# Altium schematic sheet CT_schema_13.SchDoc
size 389 x 385 mm
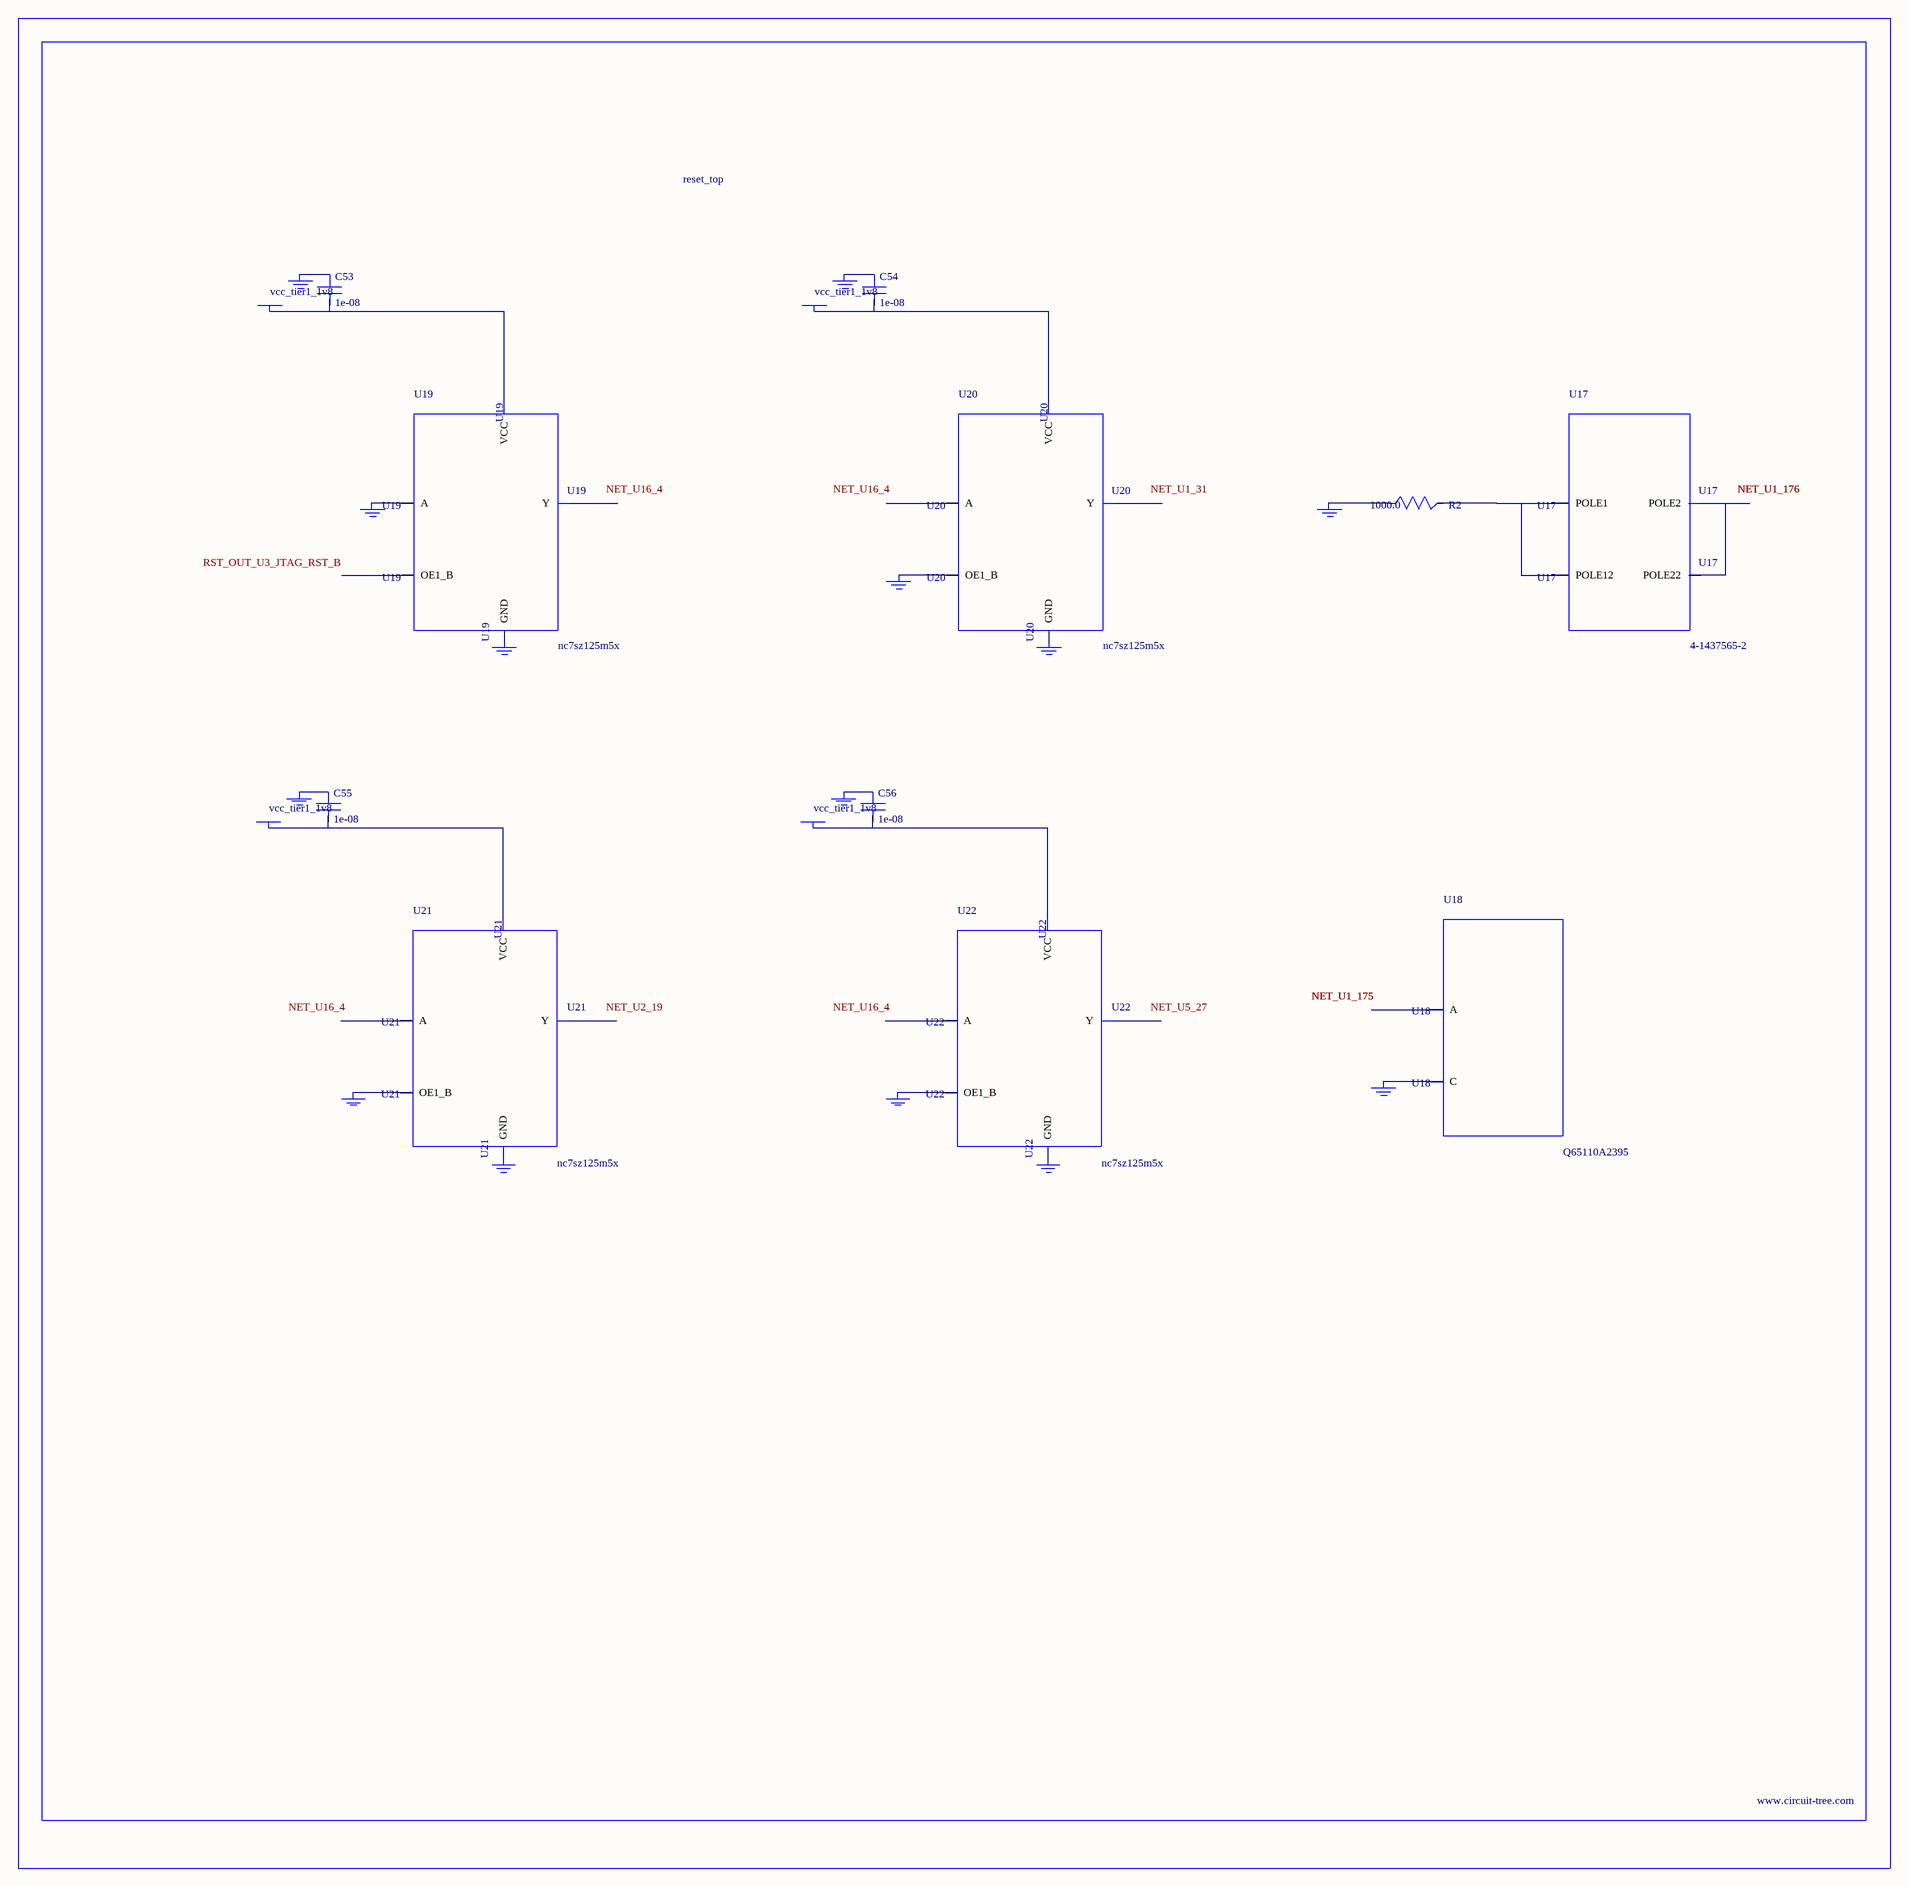
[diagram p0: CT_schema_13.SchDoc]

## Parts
BORDER12  (no value)
C53  1e-08  [C0402]
C54  1e-08  [C0402]
C55  1e-08  [C0402]
C56  1e-08  [C0402]
GND_INSTANCE_12_0  (no value)
GND_INSTANCE_12_1  (no value)
GND_INSTANCE_12_2  (no value)
GND_INSTANCE_12_3  (no value)
GND_INSTANCE_12_4  (no value)
GND_INSTANCE_12_5  (no value)
GND_INSTANCE_12_6  (no value)
GND_INSTANCE_12_7  (no value)
GND_INSTANCE_12_8  (no value)
GND_INSTANCE_12_9  (no value)
GND_INSTANCE_12_10  (no value)
GND_INSTANCE_12_11  (no value)
GND_INSTANCE_12_12  (no value)
GND_INSTANCE_12_13  (no value)
POWER_INSTANCE_12_0  vcc_tier1_1v8
POWER_INSTANCE_12_1  vcc_tier1_1v8
POWER_INSTANCE_12_2  vcc_tier1_1v8
POWER_INSTANCE_12_3  vcc_tier1_1v8
R2  1000.0  [R0603]
U17  4-1437565-2  [SW_4-1437565-2]
U18  Q65110A2395  [LGM67K-G1J2-24-Z]
U19  nc7sz125m5x  [NC7SZ125M5X]
U20  nc7sz125m5x  [NC7SZ125M5X]
U21  nc7sz125m5x  [NC7SZ125M5X]
U22  nc7sz125m5x  [NC7SZ125M5X]

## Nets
NetC53_1: C53.1 GND_INSTANCE_12_2.0(GND)
NetC53_2: C53.2 POWER_INSTANCE_12_0.0(PWR) U19.5(VCC)
NetC54_1: C54.1 GND_INSTANCE_12_5.0(GND)
NetC54_2: C54.2 POWER_INSTANCE_12_1.0(PWR) U20.5(VCC)
NetC55_1: C55.1 GND_INSTANCE_12_8.0(GND)
NetC55_2: C55.2 POWER_INSTANCE_12_2.0(PWR) U21.5(VCC)
NetC56_1: C56.1 GND_INSTANCE_12_11.0(GND)
NetC56_2: C56.2 POWER_INSTANCE_12_3.0(PWR) U22.5(VCC)
NetGND_INSTANCE_12_0_0: GND_INSTANCE_12_0.0(GND) R2.1
NetGND_INSTANCE_12_1_0: GND_INSTANCE_12_1.0(GND) U18.C
NetGND_INSTANCE_12_3_0: GND_INSTANCE_12_3.0(GND) U19.2(A)
NetGND_INSTANCE_12_4_0: GND_INSTANCE_12_4.0(GND) U19.3(GND)
NetGND_INSTANCE_12_6_0: GND_INSTANCE_12_6.0(GND) U20.1(OE1_B)
NetGND_INSTANCE_12_7_0: GND_INSTANCE_12_7.0(GND) U20.3(GND)
NetGND_INSTANCE_12_9_0: GND_INSTANCE_12_9.0(GND) U21.1(OE1_B)
NetGND_INSTANCE_12_10_0: GND_INSTANCE_12_10.0(GND) U21.3(GND)
NetGND_INSTANCE_12_12_0: GND_INSTANCE_12_12.0(GND) U22.1(OE1_B)
NetGND_INSTANCE_12_13_0: GND_INSTANCE_12_13.0(GND) U22.3(GND)
NetR2_2: R2.2 U17.1(POLE1) U17.2(POLE12)
NetU17_3: U17.3(POLE2) U17.4(POLE22)

Not connected (* = marked no-connect by the designer): U18 A; U19 1(OE1_B) 4(Y); U20 2(A) 4(Y); U21 2(A) 4(Y); U22 2(A) 4(Y)

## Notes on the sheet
- Labels drawn without touching a wire or pin: NET_U1_31, NET_U2_19, NET_U5_27, NET_U16_4, RST_OUT_U3_JTAG_RST_B

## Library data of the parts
BORDER12 = BORDER_PAGE12
C53-C56 = C0402C103K3RAC
GND_INSTANCE_12_0-GND_INSTANCE_12_13 = GND
POWER_INSTANCE_12_0-POWER_INSTANCE_12_3 = PWR
R2 = RC0603JR-071KL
